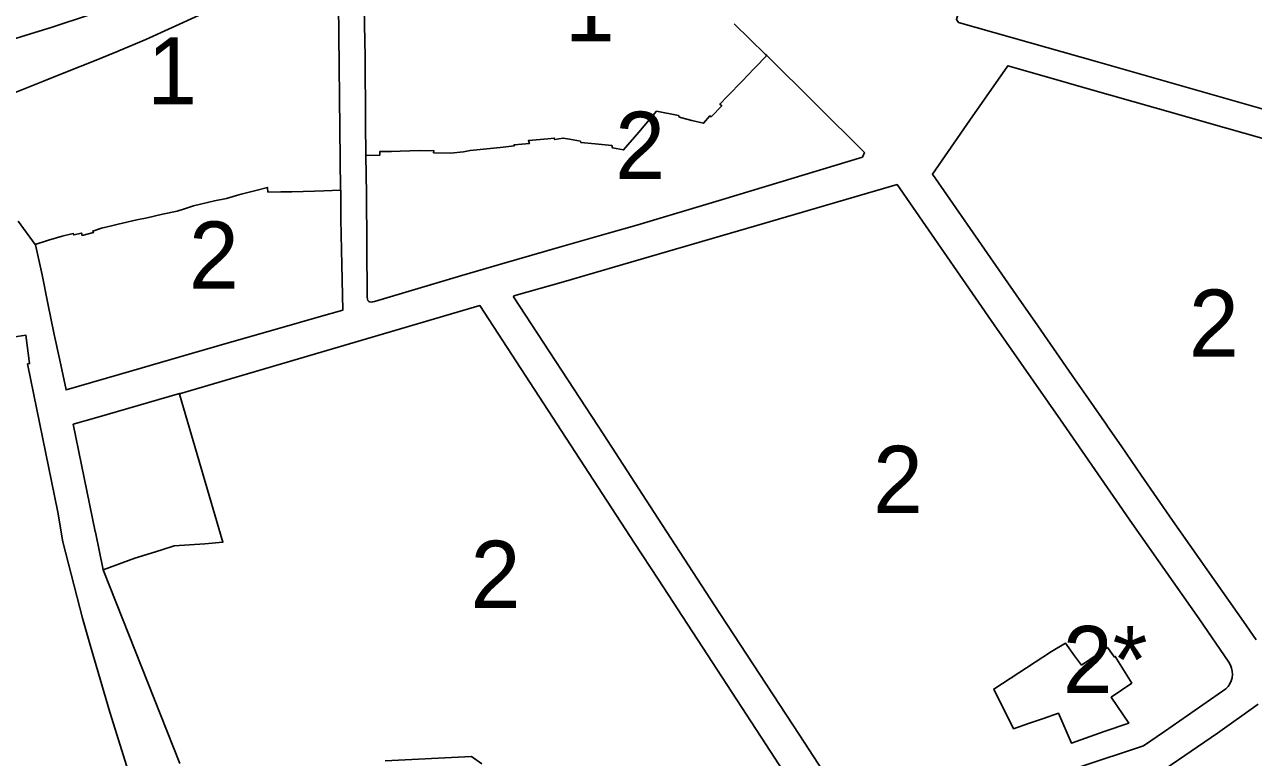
# Model space of a CAD drawing. Extents: x 598968 to 613553, y 4409678 to 4430833.
# Drawn here: x 608168.2 to 608387.9, y 4415989.2 to 4416120.2 of the extents above; entities that cross this region are included whole.
import ezdxf

# ---------------------------------------------------------------- set-up
doc = ezdxf.new("R2010")
doc.units = 0
for name, color, linetype in [('1', 7, 'Continuous'), ('ZONA 1. NUCLI ANTIC', 7, 'Continuous'), ('ZONA 2. CARRERS DE CASES. Cases de trast', 7, 'Continuous'), ("ZONA 2_. CARRERS DE CASES. Afectades a ús d'aparcament", 7, 'Continuous')]:
    doc.layers.add(name, color=color, linetype=linetype)

msp = doc.modelspace()

# ---------------------------------------------------------------- linework, layer by layer
at = {"layer": '1'}
for points in [[(608167.8621, 4416160.5525), (608178.812, 4416159.8527), (608181.062, 4416156.2328), (608181.642, 4416151.7928), (608195.0418, 4416156.183), (608210.8216, 4416161.2132), (608211.6743, 4416161.4163), (608212.5484, 4416161.4831), (608213.4221, 4416161.412), (608214.2738, 4416161.2046), (608215.0824, 4416160.8662), (608215.8279, 4416160.4051), (608216.4918, 4416159.8327), (608217.0577, 4416159.1634), (608217.5116, 4416158.4134), (608222.6315, 4416144.1136), (608213.2917, 4416138.9535), (608208.6318, 4416136.1935), (608204.0118, 4416134.0734), (608201.6679, 4416132.2379), (608196.8319, 4416129.5734), (608186.822, 4416124.3032), (608173.1222, 4416119.7631), (608156.2224, 4416114.5928)], [(608295.0508, 4416120.3852), (608300.6707, 4416114.9154), (608300.8809, 4416114.7069), (608300.8784, 4416114.7044), (608318.3457, 4416097.3759), (608317.9957, 4416096.5359), (608292.956, 4416088.9856), (608277.6562, 4416084.3753), (608272.5562, 4416082.9153), (608264.2063, 4416080.5351), (608258.8464, 4416078.9951), (608253.4965, 4416077.465), (608246.3766, 4416075.3549), (608230.7568, 4416070.7147), (608230.3968, 4416070.6447), (608230.1568, 4416070.6047), (608229.9168, 4416070.6347), (608229.6968, 4416070.7447), (608229.5368, 4416070.9246), (608229.4668, 4416071.1546), (608229.4368, 4416071.4946), (608229.2867, 4416089.9844), (608229.1816, 4416096.8443), (608229.1716, 4416098.2833), (608229.1516, 4416101.1843), (608229.1316, 4416106.4642), (608229.0815, 4416110.8542), (608229.0515, 4416114.4641), (608228.6115, 4416137.6538)], [(608224.3016, 4416123.9039), (608224.5976, 4416096.1343), (608224.6777, 4416090.7043), (608224.6793, 4416090.6026), (608224.7217, 4416090.6043), (608224.7417, 4416085.4744), (608224.8117, 4416079.9445), (608225.0517, 4416069.1846), (608220.8218, 4416067.9745), (608213.3719, 4416065.8644), (608205.192, 4416063.5043), (608197.6021, 4416061.2942), (608187.3323, 4416058.3241), (608175.5724, 4416054.9239), (608174.4624, 4416060.2138), (608173.4624, 4416064.8437), (608172.3324, 4416070.3436), (608171.3124, 4416075.5136), (608170.1124, 4416080.8535), (608170.0624, 4416080.9135), (608166.9984, 4416085.0934)], [(608166.2023, 4416107.9631), (608171.5423, 4416110.1231), (608175.5222, 4416111.7332), (608180.3882, 4416113.6533), (608184.9121, 4416115.4833), (608185.0321, 4416115.5333), (608189.868, 4416117.5934), (608194.568, 4416119.7134), (608199.2779, 4416121.8335)], [(608388.42, 4416010.2083), (608386.1, 4416013.5082), (608379.6101, 4416022.758), (608373.4601, 4416031.5677), (608367.8302, 4416039.6675), (608364.2588, 4416044.9037), (608361.8716, 4416048.3439), (608361.6952, 4416048.5981), (608358.416, 4416053.324), (608355.4902, 4416057.517), (608348.7903, 4416067.1368), (608346.0403, 4416071.1367), (608330.5004, 4416093.4962), (608337.2003, 4416103.1662), (608343.9702, 4416112.8662), (608351.3101, 4416110.7563), (608358.3701, 4416108.7465), (608370.3427, 4416105.3618), (608383.0798, 4416101.707), (608398.8996, 4416097.2173)], [(608317.9109, 4415975.9974), (608306.6912, 4415993.2808), (608291.4831, 4416016.5072), (608280.7512, 4416032.9861), (608271.7602, 4416046.8583), (608255.6114, 4416071.5651), (608255.6614, 4416071.7151), (608264.5013, 4416074.2352), (608275.1211, 4416077.3654), (608300.5306, 4416084.7402), (608324.1805, 4416091.6161), (608335.3804, 4416075.4265), (608341.5604, 4416066.5467), (608353.4203, 4416049.5771), (608366.1902, 4416031.0476), (608378.2001, 4416013.978), (608383.4951, 4416006.2132), (608383.7821, 4416005.7123), (608383.9875, 4416005.1727), (608384.1062, 4416004.6078), (608384.1355, 4416004.0313), (608384.0745, 4416003.4572), (608383.9248, 4416002.8996), (608383.69, 4416002.3722), (608383.3759, 4416001.8878), (608382.9901, 4416001.4583), (608371.9903, 4415993.8482), (608368.22, 4415991.2815), (608356.9005, 4415987.528)], [(608195.9265, 4415988.1218), (608182.2324, 4416022.7244), (608180.8336, 4416029.5023), (608180.8123, 4416029.6054), (608176.8576, 4416048.7678), (608181.0696, 4416049.9939), (608195.8589, 4416054.2993), (608195.8893, 4416054.1952), (608249.5814, 4416069.985), (608277.2313, 4416027.4861), (608281.4312, 4416021.0862), (608300.7629, 4415991.4665), (608313.5781, 4415971.7246)], [(608166.0325, 4416064.3536), (608168.3725, 4416064.7236), (608169.0425, 4416059.6237), (608168.6968, 4416059.5506), (608174.1125, 4416033.0342), (608175.0125, 4416027.7243), (608178.5025, 4416014.1195), (608179.9475, 4416009.0696), (608183.4025, 4415997.3248), (608188.2538, 4415981.8759), (608190.5711, 4415974.2871), (608191.3872, 4415971.6973), (608192.6841, 4415966.4999), (608182.4889, 4415960.1773), (608175.2977, 4415954.4502), (608171.6928, 4415950.9101), (608168.3678, 4415946.6701), (608163.2229, 4415940.6151)], [(608395.6802, 4415925.0494), (608387.7203, 4415920.9794), (608382.2114, 4415917.883), (608377.7204, 4415915.3492), (608372.9105, 4415912.4292), (608362.6506, 4415907.1491), (608352.7277, 4415922.6551), (608346.8607, 4415931.6685), (608344.0208, 4415936.0384), (608339.6508, 4415942.7582), (608333.6908, 4415951.908), (608327.9309, 4415960.7678), (608322.9409, 4415968.4476), (608337.4907, 4415973.4078), (608347.7706, 4415977.0979), (608357.8605, 4415980.7481), (608367.5403, 4415984.2582), (608370.9053, 4415986.3482), (608381.5051, 4415993.5683), (608388.74, 4415998.6984)], [(608249.9263, 4415988.0845), (608248.0723, 4415989.3664), (608232.6542, 4415988.617)]]:
    msp.add_lwpolyline(points, dxfattribs=at)
for points in [[(608360.04, 4416113.5764), (608344.6702, 4416117.9161), (608335.1803, 4416120.5959), (608334.7903, 4416121.1459), (608338.7002, 4416134.4458), (608341.5801, 4416144.2207), (608344.4901, 4416154.0757), (608359.1649, 4416149.836), (608371.8698, 4416146.1362), (608393.0146, 4416140.0417), (608408.5534, 4416135.4616), (608427.572, 4416130.2206), (608438.1341, 4416127.0227), (608449.6189, 4416123.7379), (608449.7769, 4416123.9345), (608451.4689, 4416119.658), (608443.3891, 4416107.758), (608434.7292, 4416094.798), (608429.9393, 4416093.5579), (608409.0495, 4416099.5775), (608392.1597, 4416104.3871)], [(608195.8893, 4416054.1952), (608195.8589, 4416054.2993), (608181.0696, 4416049.9939), (608176.8576, 4416048.7678), (608180.8123, 4416029.6054), (608180.8336, 4416029.5023), (608182.2324, 4416022.7244), (608187.8524, 4416024.8445), (608190.8209, 4416025.722), (608192.6879, 4416026.3156), (608194.9384, 4416027.0311), (608200.3747, 4416027.385), (608203.6242, 4416027.6661), (608195.8522, 4416054.1843)]]:
    msp.add_lwpolyline(points, close=True, dxfattribs=at)
at = {"layer": 'ZONA 1. NUCLI ANTIC'}
for points in [[(608156.2224, 4416114.5928), (608173.1222, 4416119.7631), (608186.822, 4416124.3032), (608196.8319, 4416129.5734), (608201.6679, 4416132.2379), (608204.0118, 4416134.0734), (608208.6318, 4416136.1935), (608213.2917, 4416138.9535), (608222.6315, 4416144.1136), (608217.5116, 4416158.4134), (608217.0577, 4416159.1634), (608216.4918, 4416159.8327), (608215.8279, 4416160.4051), (608215.0824, 4416160.8662), (608214.2738, 4416161.2046), (608213.4221, 4416161.412), (608212.5484, 4416161.4831), (608211.6743, 4416161.4163), (608210.8216, 4416161.2132), (608195.0418, 4416156.183), (608181.642, 4416151.7928), (608181.062, 4416156.2328), (608178.812, 4416159.8527), (608167.8621, 4416160.5525)], [(608228.6115, 4416137.6538), (608229.0515, 4416114.4641), (608229.0815, 4416110.8542), (608229.1316, 4416106.4642), (608229.1516, 4416101.1843), (608229.1716, 4416098.2833), (608229.1816, 4416096.8443), (608231.6716, 4416096.9044), (608231.7016, 4416097.5544), (608233.7915, 4416097.5144), (608235.3515, 4416097.5944), (608238.8015, 4416097.6945), (608241.3614, 4416097.6745), (608241.3115, 4416097.3145), (608244.3114, 4416097.2746), (608246.6514, 4416097.5046), (608247.8614, 4416097.7046), (608253.2313, 4416098.2547), (608255.7513, 4416098.5648), (608255.6913, 4416098.7548), (608258.4412, 4416098.9948), (608258.2712, 4416099.4948), (608261.7013, 4416099.8241), (608262.8612, 4416099.9349), (608262.9212, 4416099.6749), (608264.4412, 4416099.9349), (608265.5811, 4416099.7343), (608267.5611, 4416099.385), (608267.6311, 4416099.145), (608270.2211, 4416098.895), (608273.1911, 4416098.5951), (608273.3111, 4416098.1851), (608275.2611, 4416097.8151), (608277.9795, 4416100.999), (608281.161, 4416104.7252), (608285.0809, 4416103.9852), (608285.1909, 4416103.7152), (608285.4409, 4416103.6152), (608287.4909, 4416103.1152), (608289.5809, 4416102.6053), (608290.7209, 4416103.9253), (608290.9209, 4416103.7553), (608292.8405, 4416105.7356), (608292.4708, 4416106.0253), (608293.8408, 4416107.4453), (608296.5107, 4416110.1955), (608298.5707, 4416112.3254), (608298.7301, 4416112.486), (608300.8784, 4416114.7044), (608300.8809, 4416114.7069), (608300.6707, 4416114.9154), (608295.0508, 4416120.3852)], [(608166.9984, 4416085.0934), (608170.0624, 4416080.9135), (608172.4624, 4416081.6935), (608174.8923, 4416082.4035), (608176.8723, 4416082.8736), (608176.9423, 4416082.6236), (608178.3323, 4416082.9436), (608178.4723, 4416082.5436), (608180.4623, 4416083.0436), (608180.3423, 4416083.3236), (608181.9022, 4416083.8236), (608182.6722, 4416084.0137), (608183.9322, 4416084.3137), (608184.8722, 4416084.5437), (608188.2222, 4416085.3037), (608190.0521, 4416085.7038), (608192.8421, 4416086.3238), (608195.4621, 4416086.8638), (608195.8021, 4416086.9739), (608196.4121, 4416087.1639), (608198.372, 4416087.8139), (608202.122, 4416088.7139), (608204.252, 4416089.134), (608206.0819, 4416089.694), (608206.8919, 4416089.904), (608209.7719, 4416090.6441), (608211.5919, 4416091.1141), (608211.6719, 4416090.2841), (608213.9918, 4416090.3041), (608215.9518, 4416090.3142), (608220.0217, 4416090.4342), (608221.6917, 4416090.4843), (608224.6793, 4416090.6026), (608224.6777, 4416090.7043), (608224.5976, 4416096.1343), (608224.3016, 4416123.9039)], [(608199.2779, 4416121.8335), (608194.568, 4416119.7134), (608189.868, 4416117.5934), (608185.0321, 4416115.5333), (608184.9121, 4416115.4833), (608180.3882, 4416113.6533), (608175.5222, 4416111.7332), (608171.5423, 4416110.1231), (608166.2023, 4416107.9631)]]:
    msp.add_lwpolyline(points, dxfattribs=at)
at = {"layer": 'ZONA 2. CARRERS DE CASES. Cases de trast'}
for points in [[(608438.1341, 4416127.0227), (608427.572, 4416130.2206), (608408.5534, 4416135.4616), (608393.0146, 4416140.0417), (608371.8698, 4416146.1362), (608359.1649, 4416149.836), (608344.4901, 4416154.0757), (608341.5801, 4416144.2207), (608338.7002, 4416134.4458), (608334.7903, 4416121.1459), (608335.1803, 4416120.5959), (608344.6702, 4416117.9161), (608360.04, 4416113.5764), (608392.1597, 4416104.3871), (608409.0495, 4416099.5775), (608429.9393, 4416093.5579), (608434.7292, 4416094.798), (608443.3891, 4416107.758), (608451.4689, 4416119.658), (608449.7769, 4416123.9345), (608449.6189, 4416123.7379)], [(608229.1816, 4416096.8443), (608229.2867, 4416089.9844), (608229.4368, 4416071.4946), (608229.4668, 4416071.1546), (608229.5368, 4416070.9246), (608229.6968, 4416070.7447), (608229.9168, 4416070.6347), (608230.1568, 4416070.6047), (608230.3968, 4416070.6447), (608230.7568, 4416070.7147), (608246.3766, 4416075.3549), (608253.4965, 4416077.465), (608258.8464, 4416078.9951), (608264.2063, 4416080.5351), (608272.5562, 4416082.9153), (608277.6562, 4416084.3753), (608292.956, 4416088.9856), (608317.9957, 4416096.5359), (608318.3457, 4416097.3759), (608300.8784, 4416114.7044), (608298.7301, 4416112.486), (608298.5707, 4416112.3254), (608296.5107, 4416110.1955), (608293.8408, 4416107.4453), (608292.4708, 4416106.0253), (608292.8405, 4416105.7356), (608290.9209, 4416103.7553), (608290.7209, 4416103.9253), (608289.5809, 4416102.6053), (608287.4909, 4416103.1152), (608285.4409, 4416103.6152), (608285.1909, 4416103.7152), (608285.0809, 4416103.9852), (608281.161, 4416104.7252), (608277.9795, 4416100.999), (608275.2611, 4416097.8151), (608273.3111, 4416098.1851), (608273.1911, 4416098.5951), (608270.2211, 4416098.895), (608267.6311, 4416099.145), (608267.5611, 4416099.385), (608265.5811, 4416099.7343), (608264.4412, 4416099.9349), (608262.9212, 4416099.6749), (608262.8612, 4416099.9349), (608261.7013, 4416099.8241), (608258.2712, 4416099.4948), (608258.4412, 4416098.9948), (608255.6913, 4416098.7548), (608255.7513, 4416098.5648), (608253.2313, 4416098.2547), (608247.8614, 4416097.7046), (608246.6514, 4416097.5046), (608244.3114, 4416097.2746), (608241.3115, 4416097.3145), (608241.3614, 4416097.6745), (608238.8015, 4416097.6945), (608235.3515, 4416097.5944), (608233.7915, 4416097.5144), (608231.7016, 4416097.5544), (608231.6716, 4416096.9044)], [(608224.6793, 4416090.6026), (608221.6917, 4416090.4843), (608220.0217, 4416090.4342), (608215.9518, 4416090.3142), (608213.9918, 4416090.3041), (608211.6719, 4416090.2841), (608211.5919, 4416091.1141), (608209.7719, 4416090.6441), (608206.8919, 4416089.904), (608206.0819, 4416089.694), (608204.252, 4416089.134), (608202.122, 4416088.7139), (608198.372, 4416087.8139), (608196.4121, 4416087.1639), (608195.8021, 4416086.9739), (608195.4621, 4416086.8638), (608192.8421, 4416086.3238), (608190.0521, 4416085.7038), (608188.2222, 4416085.3037), (608184.8722, 4416084.5437), (608183.9322, 4416084.3137), (608182.6722, 4416084.0137), (608181.9022, 4416083.8236), (608180.3423, 4416083.3236), (608180.4623, 4416083.0436), (608178.4723, 4416082.5436), (608178.3323, 4416082.9436), (608176.9423, 4416082.6236), (608176.8723, 4416082.8736), (608174.8923, 4416082.4035), (608172.4624, 4416081.6935), (608170.0624, 4416080.9135), (608170.1124, 4416080.8535), (608171.3124, 4416075.5136), (608172.3324, 4416070.3436), (608173.4624, 4416064.8437), (608174.4624, 4416060.2138), (608175.5724, 4416054.9239), (608187.3323, 4416058.3241), (608197.6021, 4416061.2942), (608205.192, 4416063.5043), (608213.3719, 4416065.8644), (608220.8218, 4416067.9745), (608225.0517, 4416069.1846), (608224.8117, 4416079.9445), (608224.7417, 4416085.4744), (608224.7217, 4416090.6043)], [(608355.9004, 4416007.3777), (608357.1658, 4416005.7035), (608361.8003, 4416008.8778), (608363.0403, 4416007.1579), (608363.1803, 4416007.2679), (608364.6703, 4416004.8379), (608366.1503, 4416002.508), (608362.4404, 4415999.9779), (608365.6203, 4415995.348), (608361.241, 4415993.8282), (608355.3505, 4415991.7679), (608353.0305, 4415997.1078), (608350.3399, 4415996.1876), (608347.7005, 4415995.2777), (608345.0106, 4415994.3377), (608341.4542, 4416001.4212), (608351.7637, 4416008.1505), (608354.2904, 4416009.6477)]]:
    msp.add_lwpolyline(points, close=True, dxfattribs=at)
for points in [[(608398.8996, 4416097.2173), (608383.0798, 4416101.707), (608370.3427, 4416105.3618), (608358.3701, 4416108.7465), (608351.3101, 4416110.7563), (608343.9702, 4416112.8662), (608337.2003, 4416103.1662), (608330.5004, 4416093.4962), (608346.0403, 4416071.1367), (608348.7903, 4416067.1368), (608355.4902, 4416057.517), (608358.416, 4416053.324), (608361.6952, 4416048.5981), (608361.8716, 4416048.3439), (608364.2588, 4416044.9037), (608367.8302, 4416039.6675), (608373.4601, 4416031.5677), (608379.6101, 4416022.758), (608386.1, 4416013.5082), (608388.42, 4416010.2083)], [(608356.9005, 4415987.528), (608368.22, 4415991.2815), (608371.9903, 4415993.8482), (608382.9901, 4416001.4583), (608383.3759, 4416001.8878), (608383.69, 4416002.3722), (608383.9248, 4416002.8996), (608384.0745, 4416003.4572), (608384.1355, 4416004.0313), (608384.1062, 4416004.6078), (608383.9875, 4416005.1727), (608383.7821, 4416005.7123), (608383.4951, 4416006.2132), (608378.2001, 4416013.978), (608366.1902, 4416031.0476), (608353.4203, 4416049.5771), (608341.5604, 4416066.5467), (608335.3804, 4416075.4265), (608324.1805, 4416091.6161), (608300.5306, 4416084.7402), (608275.1211, 4416077.3654), (608264.5013, 4416074.2352), (608255.6614, 4416071.7151), (608255.6114, 4416071.5651), (608271.7602, 4416046.8583), (608280.7512, 4416032.9861), (608291.4831, 4416016.5072), (608306.6912, 4415993.2808), (608317.9109, 4415975.9974)], [(608313.5781, 4415971.7246), (608300.7629, 4415991.4665), (608281.4312, 4416021.0862), (608277.2313, 4416027.4861), (608249.5814, 4416069.985), (608195.8893, 4416054.1952), (608195.8522, 4416054.1843), (608203.6242, 4416027.6661), (608200.3747, 4416027.385), (608194.9384, 4416027.0311), (608192.6879, 4416026.3156), (608190.8209, 4416025.722), (608187.8524, 4416024.8445), (608182.2324, 4416022.7244), (608195.9265, 4415988.1218)], [(608163.2229, 4415940.6151), (608168.3678, 4415946.6701), (608171.6928, 4415950.9101), (608175.2977, 4415954.4502), (608182.4889, 4415960.1773), (608192.6841, 4415966.4999), (608191.3872, 4415971.6973), (608190.5711, 4415974.2871), (608188.2538, 4415981.8759), (608183.4025, 4415997.3248), (608179.9475, 4416009.0696), (608178.5025, 4416014.1195), (608175.0125, 4416027.7243), (608174.1125, 4416033.0342), (608168.6968, 4416059.5506), (608169.0425, 4416059.6237), (608168.3725, 4416064.7236), (608166.0325, 4416064.3536)], [(608388.74, 4415998.6984), (608381.5051, 4415993.5683), (608370.9053, 4415986.3482), (608367.5403, 4415984.2582), (608357.8605, 4415980.7481), (608347.7706, 4415977.0979), (608337.4907, 4415973.4078), (608322.9409, 4415968.4476), (608327.9309, 4415960.7678), (608333.6908, 4415951.908), (608339.6508, 4415942.7582), (608344.0208, 4415936.0384), (608346.8607, 4415931.6685), (608352.7277, 4415922.6551), (608362.6506, 4415907.1491), (608372.9105, 4415912.4292), (608377.7204, 4415915.3492), (608382.2114, 4415917.883), (608387.7203, 4415920.9794), (608395.6802, 4415925.0494)], [(608232.6542, 4415988.617), (608248.0723, 4415989.3664), (608249.9263, 4415988.0845)]]:
    msp.add_lwpolyline(points, dxfattribs=at)
at = {"layer": "ZONA 2_. CARRERS DE CASES. Afectades a ús d'aparcament"}
msp.add_lwpolyline([(608355.9004, 4416007.3777), (608354.2904, 4416009.6477), (608351.7637, 4416008.1505), (608341.4542, 4416001.4212), (608345.0106, 4415994.3377), (608347.7005, 4415995.2777), (608350.3399, 4415996.1876), (608353.0305, 4415997.1078), (608355.3505, 4415991.7679), (608361.241, 4415993.8282), (608365.6203, 4415995.348), (608362.4404, 4415999.9779), (608366.1503, 4416002.508), (608364.6703, 4416004.8379), (608363.1803, 4416007.2679), (608363.0403, 4416007.1579), (608361.8003, 4416008.8778), (608357.1658, 4416005.7035)], close=True, dxfattribs=at)

# ---------------------------------------------------------------- texts
at = {"layer": 'ZONA 1. NUCLI ANTIC'}
for p in [(608264.7462, 4416117.2491), (608190.0959, 4416105.9736)]:
    msp.add_text('1', height=12, dxfattribs=at).set_placement(p)
at = {"layer": 'ZONA 2. CARRERS DE CASES. Cases de trast'}
for p in [(608273.7637, 4416092.6546), (608197.557, 4416073.019), (608376.3749, 4416060.852), (608319.8734, 4416032.9218), (608247.9052, 4416015.951)]:
    msp.add_text('2', height=12, dxfattribs=at).set_placement(p)
at = {"layer": "ZONA 2_. CARRERS DE CASES. Afectades a ús d'aparcament"}
msp.add_text('2*', height=12, dxfattribs=at).set_placement((608353.8022, 4416000.7078))

doc.saveas('drawing.dxf')
